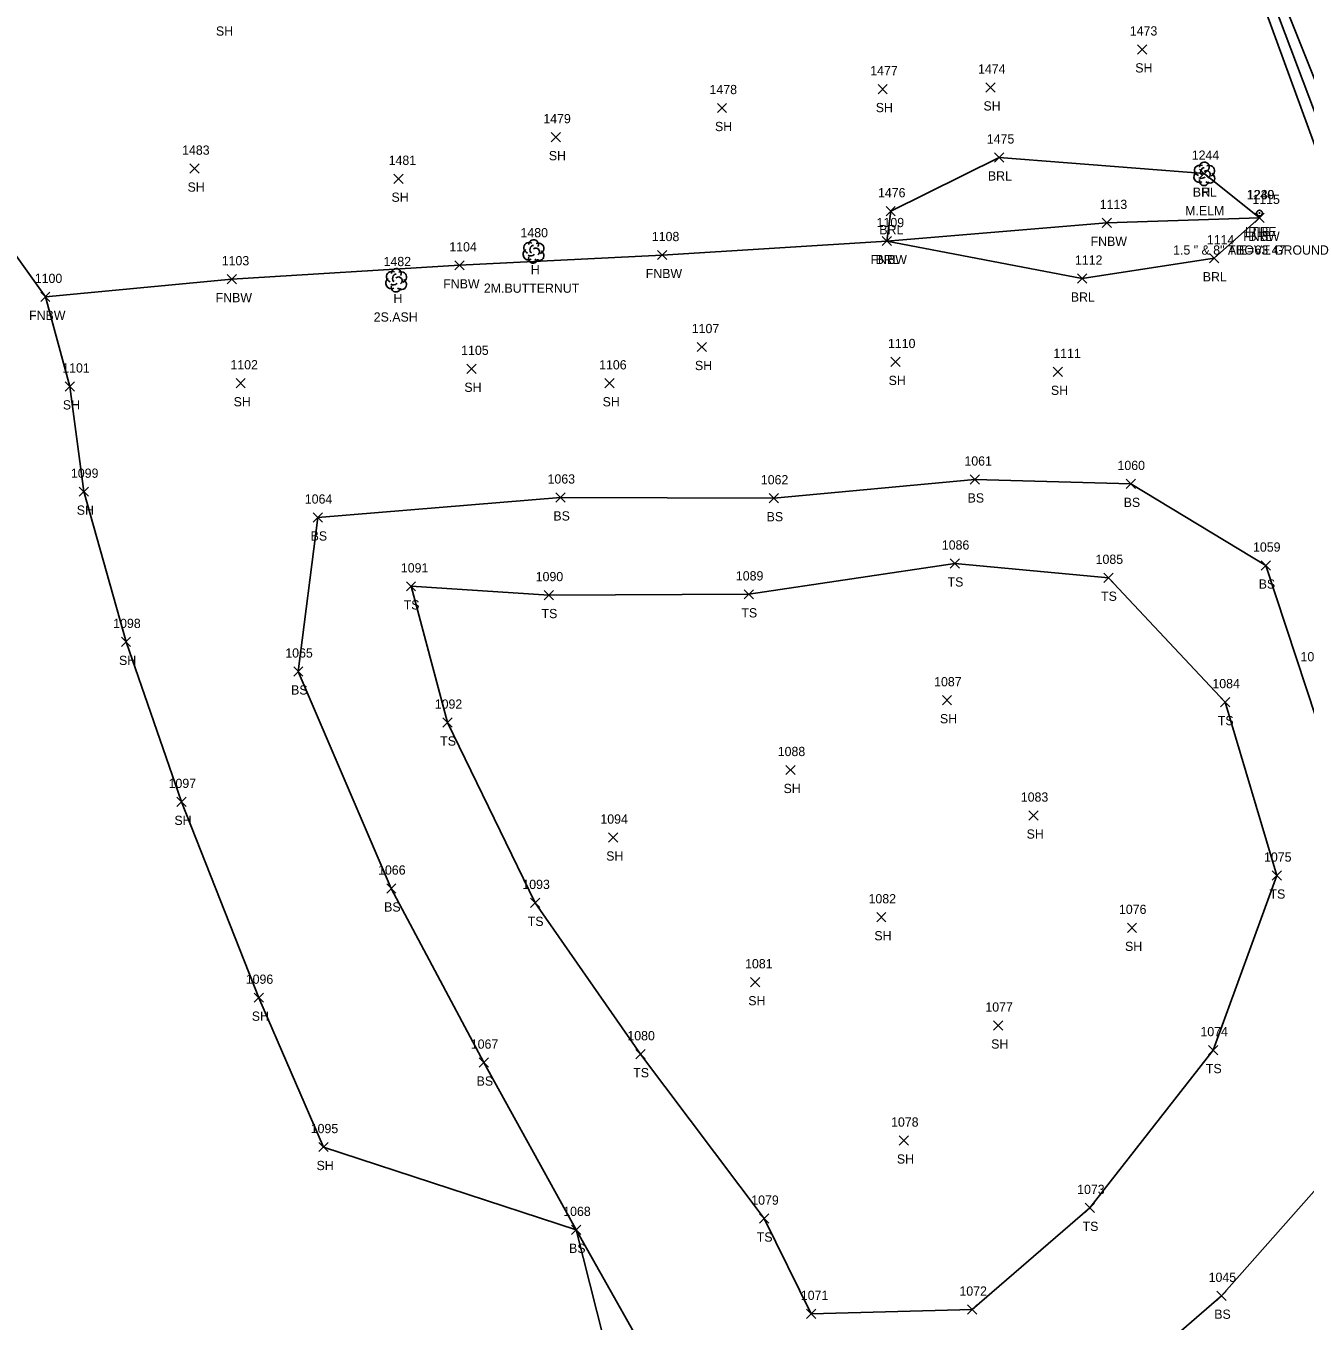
# Model space of a CAD drawing. Extents: x 1472233 to 1475777, y 540726 to 543442.
# Drawn here: x 1475042.8 to 1475319.7, y 542338.7 to 542619 of the extents above; entities that cross this region are included whole.
import ezdxf

# ---------------------------------------------------------------- set-up
doc = ezdxf.new("R2010")
doc.units = 0
for name, color, linetype in [('C_A', 7, 'Continuous'), ('C_C', 7, 'Continuous'), ('C_I', 7, 'Continuous'), ('CBP', 7, 'Continuous'), ('L_A', 7, 'Continuous'), ('L_C', 7, 'Continuous'), ('L_I', 7, 'Continuous'), ('L_TIC', 7, 'Continuous'), ('LABL', 7, 'Continuous'), ('LELB', 7, 'Continuous'), ('LFNC', 7, 'Continuous'), ('LSOGP', 7, 'Continuous'), ('LTD', 7, 'Continuous'), ('M_A', 7, 'Continuous'), ('M_C', 7, 'Continuous'), ('M_I', 7, 'Continuous'), ('MPIP', 7, 'Continuous'), ('PEU', 7, 'Continuous')]:
    doc.layers.add(name, color=color, linetype=linetype)

msp = doc.modelspace()

# ---------------------------------------------------------------- linework, layer by layer
at = {"layer": 'CBP'}
for radius in [0.625, 0.0833]:
    msp.add_circle((1475309.83, 542578.54), radius, dxfattribs=at)
at = {"layer": 'L_TIC'}
for points in [[(1475283.45, 542612.96), (1475285.45, 542614.96)], [(1475285.45, 542612.96), (1475283.45, 542614.96)], [(1475227.27, 542604.37), (1475229.27, 542606.37)], [(1475229.27, 542604.37), (1475227.27, 542606.37)], [(1475250.59, 542604.73), (1475252.59, 542606.73)], [(1475252.59, 542604.73), (1475250.59, 542606.73)], [(1475192.48, 542600.27), (1475194.48, 542602.27)], [(1475194.48, 542600.27), (1475192.48, 542602.27)], [(1475156.51, 542593.97), (1475158.51, 542595.97)], [(1475158.51, 542593.97), (1475156.51, 542595.97)], [(1475252.5, 542589.58), (1475254.5, 542591.58)], [(1475254.5, 542589.58), (1475252.5, 542591.58)], [(1475078.32, 542587.16), (1475080.32, 542589.16)], [(1475080.32, 542587.16), (1475078.32, 542589.16)], [(1475122.46, 542584.97), (1475124.46, 542586.97)], [(1475124.46, 542584.97), (1475122.46, 542586.97)], [(1475296.85, 542586.07), (1475298.85, 542588.07)], [(1475298.85, 542586.07), (1475296.85, 542588.07)], [(1475229, 542577.94), (1475231, 542579.94)], [(1475231, 542577.94), (1475229, 542579.94)], [(1475229, 542577.94), (1475231, 542579.94)], [(1475231, 542577.94), (1475229, 542579.94)], [(1475275.8, 542575.41), (1475277.8, 542577.41)], [(1475277.8, 542575.41), (1475275.8, 542577.41)], [(1475308.85, 542576.51), (1475310.85, 542578.51)], [(1475310.85, 542576.51), (1475308.85, 542578.51)], [(1475308.85, 542576.51), (1475310.85, 542578.51)], [(1475310.85, 542576.51), (1475308.85, 542578.51)], [(1475228.16, 542571.49), (1475230.16, 542573.49)], [(1475230.16, 542571.49), (1475228.16, 542573.49)], [(1475228.16, 542571.49), (1475230.16, 542573.49)], [(1475230.16, 542571.49), (1475228.16, 542573.49)], [(1475228.16, 542571.49), (1475230.16, 542573.49)], [(1475230.16, 542571.49), (1475228.16, 542573.49)], [(1475179.51, 542568.46), (1475181.51, 542570.46)], [(1475181.51, 542568.46), (1475179.51, 542570.46)], [(1475299, 542567.76), (1475301, 542569.76)], [(1475301, 542567.76), (1475299, 542569.76)], [(1475135.67, 542566.23), (1475137.67, 542568.23)], [(1475137.67, 542566.23), (1475135.67, 542568.23)], [(1475086.41, 542563.23), (1475088.41, 542565.23)], [(1475088.41, 542563.23), (1475086.41, 542565.23)], [(1475270.44, 542563.37), (1475272.44, 542565.37)], [(1475272.44, 542563.37), (1475270.44, 542565.37)], [(1475046.02, 542559.41), (1475048.02, 542561.41)], [(1475048.02, 542559.41), (1475046.02, 542561.41)], [(1475188.14, 542548.55), (1475190.14, 542550.55)], [(1475190.14, 542548.55), (1475188.14, 542550.55)], [(1475230.06, 542545.32), (1475232.06, 542547.32)], [(1475232.06, 542545.32), (1475230.06, 542547.32)], [(1475138.24, 542543.84), (1475140.24, 542545.84)], [(1475140.24, 542543.84), (1475138.24, 542545.84)], [(1475265.2, 542543.18), (1475267.2, 542545.18)], [(1475267.2, 542543.18), (1475265.2, 542545.18)], [(1475051.32, 542540.03), (1475053.32, 542542.03)], [(1475053.32, 542540.03), (1475051.32, 542542.03)], [(1475088.29, 542540.71), (1475090.29, 542542.71)], [(1475090.29, 542540.71), (1475088.29, 542542.71)], [(1475168.15, 542540.7), (1475170.15, 542542.7)], [(1475170.15, 542540.7), (1475168.15, 542542.7)], [(1475247.21, 542519.89), (1475249.21, 542521.89)], [(1475249.21, 542519.89), (1475247.21, 542521.89)], [(1475280.99, 542518.93), (1475282.99, 542520.93)], [(1475282.99, 542518.93), (1475280.99, 542520.93)], [(1475054.34, 542517.25), (1475056.34, 542519.25)], [(1475056.34, 542517.25), (1475054.34, 542519.25)], [(1475157.55, 542516), (1475159.55, 542518)], [(1475159.55, 542516), (1475157.55, 542518)], [(1475203.7, 542515.83), (1475205.7, 542517.83)], [(1475205.7, 542515.83), (1475203.7, 542517.83)], [(1475105, 542511.66), (1475107, 542513.66)], [(1475107, 542511.66), (1475105, 542513.66)], [(1475242.9, 542501.71), (1475244.9, 542503.71)], [(1475244.9, 542501.71), (1475242.9, 542503.71)], [(1475310.21, 542501.26), (1475312.21, 542503.26)], [(1475312.21, 542501.26), (1475310.21, 542503.26)], [(1475125.17, 542496.76), (1475127.17, 542498.76)], [(1475127.17, 542496.76), (1475125.17, 542498.76)], [(1475276.13, 542498.62), (1475278.13, 542500.62)], [(1475278.13, 542498.62), (1475276.13, 542500.62)], [(1475155.01, 542494.87), (1475157.01, 542496.87)], [(1475157.01, 542494.87), (1475155.01, 542496.87)], [(1475198.27, 542495.03), (1475200.27, 542497.03)], [(1475200.27, 542495.03), (1475198.27, 542497.03)], [(1475063.48, 542484.74), (1475065.48, 542486.74)], [(1475065.48, 542484.74), (1475063.48, 542486.74)], [(1475100.78, 542478.34), (1475102.78, 542480.34)], [(1475102.78, 542478.34), (1475100.78, 542480.34)], [(1475241.18, 542472.12), (1475243.18, 542474.12)], [(1475243.18, 542472.12), (1475241.18, 542474.12)], [(1475301.4, 542471.71), (1475303.4, 542473.71)], [(1475303.4, 542471.71), (1475301.4, 542473.71)], [(1475133.08, 542467.28), (1475135.08, 542469.28)], [(1475135.08, 542467.28), (1475133.08, 542469.28)], [(1475207.32, 542457.02), (1475209.32, 542459.02)], [(1475209.32, 542457.02), (1475207.32, 542459.02)], [(1475075.47, 542450.12), (1475077.47, 542452.12)], [(1475077.47, 542450.12), (1475075.47, 542452.12)], [(1475259.93, 542447.16), (1475261.93, 542449.16)], [(1475261.93, 542447.16), (1475259.93, 542449.16)], [(1475168.94, 542442.4), (1475170.94, 542444.4)], [(1475170.94, 542442.4), (1475168.94, 542444.4)], [(1475312.59, 542434.17), (1475314.59, 542436.17)], [(1475314.59, 542434.17), (1475312.59, 542436.17)], [(1475120.91, 542431.37), (1475122.91, 542433.37)], [(1475122.91, 542431.37), (1475120.91, 542433.37)], [(1475152.04, 542428.26), (1475154.04, 542430.26)], [(1475154.04, 542428.26), (1475152.04, 542430.26)], [(1475152.04, 542428.26), (1475154.04, 542430.26)], [(1475154.04, 542428.26), (1475152.04, 542430.26)], [(1475226.98, 542425.15), (1475228.98, 542427.15)], [(1475228.98, 542425.15), (1475226.98, 542427.15)], [(1475281.23, 542422.86), (1475283.23, 542424.86)], [(1475283.23, 542422.86), (1475281.23, 542424.86)], [(1475199.68, 542411.09), (1475201.68, 542413.09)], [(1475201.68, 542411.09), (1475199.68, 542413.09)], [(1475092.22, 542407.74), (1475094.22, 542409.74)], [(1475094.22, 542407.74), (1475092.22, 542409.74)], [(1475252.26, 542401.72), (1475254.26, 542403.72)], [(1475254.26, 542401.72), (1475252.26, 542403.72)], [(1475298.81, 542396.4), (1475300.81, 542398.4)], [(1475300.81, 542396.4), (1475298.81, 542398.4)], [(1475140.93, 542393.7), (1475142.93, 542395.7)], [(1475142.93, 542393.7), (1475140.93, 542395.7)], [(1475174.86, 542395.51), (1475176.86, 542397.51)], [(1475176.86, 542395.51), (1475174.86, 542397.51)], [(1475231.86, 542376.83), (1475233.86, 542378.83)], [(1475233.86, 542376.83), (1475231.86, 542378.83)], [(1475106.23, 542375.42), (1475108.23, 542377.42)], [(1475108.23, 542375.42), (1475106.23, 542377.42)], [(1475272.13, 542362.25), (1475274.13, 542364.25)], [(1475274.13, 542362.25), (1475272.13, 542364.25)], [(1475201.6, 542359.93), (1475203.6, 542361.93)], [(1475203.6, 542359.93), (1475201.6, 542361.93)], [(1475160.94, 542357.5), (1475162.94, 542359.5)], [(1475162.94, 542357.5), (1475160.94, 542359.5)], [(1475300.6, 542343.24), (1475302.6, 542345.24)], [(1475302.6, 542343.24), (1475300.6, 542345.24)], [(1475246.65, 542340.25), (1475248.65, 542342.25)], [(1475248.65, 542340.25), (1475246.65, 542342.25)], [(1475211.76, 542339.33), (1475213.76, 542341.33)], [(1475213.76, 542339.33), (1475211.76, 542341.33)], [(1475211.76, 542339.33), (1475213.76, 542341.33)], [(1475213.76, 542339.33), (1475211.76, 542341.33)]]:
    msp.add_lwpolyline(points, dxfattribs=at)
at = {"layer": 'LABL'}
for points in [[(1475229.16, 542572.49), (1475271.44, 542564.37), (1475300, 542568.76), (1475309.85, 542577.51), (1475297.85, 542587.07), (1475253.5, 542590.58), (1475230, 542578.94)], [(1475229.16, 542572.49), (1475230, 542578.94)]]:
    msp.add_lwpolyline(points, dxfattribs=at)
at = {"layer": 'LELB'}
for points in [[(1475471.07, 542235.32), (1475455.73, 542277.51), (1475442.16, 542311.63), (1475427.2, 542345.14), (1475407.3, 542390.99), (1475390.5, 542430.83), (1475365.35, 542490.83), (1475345.68, 542538.17), (1475324.25, 542586.46), (1475305.93, 542636.69)], [(1475477.4, 542237.46), (1475459.38, 542278.29), (1475445.09, 542313.25), (1475430.15, 542346.36), (1475410.48, 542391.41), (1475393.47, 542431.66), (1475368.2, 542491.05), (1475347.92, 542539.36), (1475326.62, 542587.53), (1475308.04, 542636.9)], [(1475200.77, 542308.82), (1475241.78, 542316.68), (1475274.04, 542320.33), (1475301.6, 542344.24), (1475328.33, 542374.36), (1475336.87, 542408.47), (1475330.86, 542442.76), (1475311.21, 542502.26), (1475281.99, 542519.93), (1475248.21, 542520.89), (1475204.7, 542516.83), (1475158.55, 542517), (1475106, 542512.66), (1475101.78, 542479.34), (1475121.91, 542432.37), (1475141.93, 542394.7), (1475161.94, 542358.5), (1475181.79, 542323.33), (1475176.76, 542299.8)], [(1475212.76, 542340.33), (1475247.65, 542341.25), (1475273.13, 542363.25), (1475299.81, 542397.4), (1475313.59, 542435.17), (1475302.4, 542472.71), (1475277.13, 542499.62), (1475243.9, 542502.71), (1475199.27, 542496.03), (1475156.01, 542495.87), (1475126.17, 542497.76), (1475134.08, 542468.28), (1475153.04, 542429.26)], [(1475212.76, 542340.33), (1475202.6, 542360.93), (1475175.86, 542396.51), (1475153.04, 542429.26)]]:
    msp.add_lwpolyline(points, dxfattribs=at)
at = {"layer": 'LFNC'}
msp.add_lwpolyline([(1475047.02, 542560.41), (1475087.41, 542564.23), (1475136.67, 542567.23), (1475180.51, 542569.46), (1475229.16, 542572.49), (1475276.8, 542576.41), (1475309.85, 542577.51)], dxfattribs=at)
at = {"layer": 'LSOGP'}
msp.add_lwpolyline([(1475330.12, 542185), (1475316.58, 542176.31), (1475298.4, 542207.53), (1475277.61, 542235.83), (1475254.76, 542251.05), (1475228.37, 542269.02), (1475176.76, 542299.8), (1475161.94, 542358.5), (1475107.23, 542376.42), (1475093.22, 542408.74), (1475076.47, 542451.12), (1475064.48, 542485.74), (1475055.34, 542518.25), (1475052.32, 542541.03), (1475047.02, 542560.41), (1475029.67, 542584.63)], dxfattribs=at)
at = {"layer": 'LTD'}
for p, q in [((1475297.85, 542587.07), (1475297.85, 542587.07)), ((1475297.85, 542587.07), (1475297.85, 542587.07)), ((1475152.65, 542570.29), (1475152.65, 542570.29)), ((1475152.65, 542570.29), (1475152.65, 542570.29)), ((1475122.92, 542564.05), (1475122.92, 542564.05)), ((1475122.92, 542564.05), (1475122.92, 542564.05))]:
    msp.add_line(p, q, dxfattribs=at)
for centre in [(1475297.9, 542588.5), (1475152.7, 542571.73), (1475122.97, 542565.48)]:
    msp.add_arc(centre, 1.05, 335.5272, 180.9563, dxfattribs=at)
for centre, major_axis, ratio, start_param, end_param in [((1475297.06, 542587.73), (1.21, -0.51), 0.895232, 1.570796, 4.712389), ((1475297.64, 542587.53), (-0.208, -0.792), 0.645439, 3.141593, 6.283185), ((1475298.89, 542587.65), (-1.14, -0.48), 0.949671, 1.570796, 4.712389), ((1475296.77, 542586.36), (0.58, -1.04), 0.959034, 3.141593, 6.283185), ((1475297.85, 542585.57), (0.26, 1.06), 0.942809, 1.570796, 4.712389), ((1475297.39, 542586.32), (-0.625, -0.083), 0.423636, 0, 3.141593), ((1475298.35, 542586.9), (-0.5, 0.667), 0.989748, 3.141593, 6.283185), ((1475298.85, 542586.24), (-1.09, 0.79), 0.841452, 1.570796, 4.712389), ((1475151.86, 542570.96), (1.21, -0.51), 0.895232, 1.570796, 4.712389), ((1475152.44, 542570.75), (-0.208, -0.792), 0.645439, 3.141593, 6.283185), ((1475153.69, 542570.88), (-1.14, -0.48), 0.949671, 1.570796, 4.712389), ((1475151.57, 542569.58), (0.58, -1.04), 0.959034, 3.141593, 6.283185), ((1475152.65, 542568.79), (0.26, 1.06), 0.942809, 1.570796, 4.712389), ((1475152.19, 542569.54), (-0.625, -0.083), 0.423636, 0, 3.141593), ((1475153.15, 542570.13), (-0.5, 0.667), 0.989748, 3.141593, 6.283185), ((1475153.65, 542569.46), (-1.09, 0.79), 0.841452, 1.570796, 4.712389), ((1475122.13, 542564.71), (1.21, -0.51), 0.895232, 1.570796, 4.712389), ((1475123.97, 542564.63), (-1.14, -0.48), 0.949671, 1.570796, 4.712389), ((1475121.84, 542563.34), (0.58, -1.04), 0.959034, 3.141593, 6.283185), ((1475122.47, 542563.3), (-0.625, -0.083), 0.423636, 0, 3.141593), ((1475122.72, 542564.5), (-0.208, -0.792), 0.645439, 3.141593, 6.283185), ((1475123.42, 542563.88), (-0.5, 0.667), 0.989748, 3.141593, 6.283185), ((1475123.92, 542563.21), (-1.09, 0.79), 0.841452, 1.570796, 4.712389), ((1475122.92, 542562.55), (0.26, 1.06), 0.942809, 1.570796, 4.712389)]:
    msp.add_ellipse(centre, major_axis=major_axis, ratio=ratio, start_param=start_param, end_param=end_param, dxfattribs=at)
at = {"layer": 'MPIP'}
for radius in [0.625, 0.0833]:
    msp.add_circle((1475309.83, 542578.54), radius, dxfattribs=at)
at = {"layer": 'PEU'}
msp.add_lwpolyline([(1475479.12, 542237.85), (1475461.93, 542278.83), (1475446.81, 542314.13), (1475433.04, 542347.65), (1475413.19, 542392.06), (1475396.09, 542432.46), (1475370.67, 542491.66), (1475350.46, 542540.4), (1475329.23, 542588.78), (1475309.74, 542637.56), (1475293.45, 542677.97), (1475275.03, 542722.66), (1475253.25, 542774.01), (1475237.56, 542813.36), (1475220.2, 542854.42), (1475196.99, 542908.72), (1475177.68, 542952.09), (1475158.12, 543000.84), (1475137.1, 543050.15), (1475113.34, 543107.63), (1475097.32, 543147.51)], dxfattribs=at)

# ---------------------------------------------------------------- texts
at = {"layer": 'C_A'}
msp.add_text('TIE', height=2, dxfattribs=at).set_placement((1475307.91, 542573.54))
at = {"layer": 'C_C'}
msp.add_text('TIE=63.47', height=2, dxfattribs=at).set_placement((1475303.01, 542569.54))
at = {"layer": 'C_I'}
msp.add_text('1240', height=2, dxfattribs=at).set_placement((1475307.05, 542581.54))
at = {"layer": 'L_A'}
for s, p in [('SH', (1475083.95, 542616.93)), ('SH', (1475282.94, 542608.96)), ('SH', (1475226.76, 542600.37)), ('SH', (1475250.08, 542600.73)), ('SH', (1475191.97, 542596.27)), ('SH', (1475156, 542589.97)), ('BRL', (1475251.04, 542585.58)), ('SH', (1475077.8, 542583.16)), ('SH', (1475121.95, 542580.97)), ('BRL', (1475295.39, 542582.07)), ('H', (1475297.28, 542582.07)), ('BRL', (1475227.54, 542573.94)), ('BRL', (1475227.54, 542573.94)), ('FNBW', (1475306.32, 542572.51)), ('BRL', (1475307.4, 542572.51)), ('FNBW', (1475273.27, 542571.41)), ('FNBW', (1475225.64, 542567.49)), ('BRL', (1475226.71, 542567.49)), ('BRL', (1475226.71, 542567.49)), ('H', (1475152.09, 542565.29)), ('FNBW', (1475176.98, 542564.46)), ('BRL', (1475297.55, 542563.76)), ('FNBW', (1475133.14, 542562.23)), ('FNBW', (1475083.88, 542559.23)), ('H', (1475122.36, 542559.05)), ('BRL', (1475268.99, 542559.37)), ('FNBW', (1475043.5, 542555.41)), ('SH', (1475187.63, 542544.55)), ('SH', (1475229.55, 542541.32)), ('SH', (1475137.72, 542539.84)), ('SH', (1475264.68, 542539.18)), ('SH', (1475050.81, 542536.03)), ('SH', (1475087.78, 542536.71)), ('SH', (1475167.64, 542536.7)), ('SH', (1475053.82, 542513.25)), ('BS', (1475246.65, 542515.89)), ('BS', (1475280.43, 542514.93)), ('BS', (1475156.99, 542512)), ('BS', (1475203.15, 542511.83)), ('BS', (1475104.44, 542507.66)), ('TS', (1475242.31, 542497.71)), ('BS', (1475309.65, 542497.26)), ('TS', (1475275.54, 542494.62)), ('TS', (1475124.58, 542492.76)), ('TS', (1475154.42, 542490.87)), ('TS', (1475197.68, 542491.03)), ('SH', (1475062.97, 542480.74)), ('BS', (1475100.22, 542474.34)), ('SH', (1475240.66, 542468.12)), ('TS', (1475300.81, 542467.71)), ('TS', (1475132.49, 542463.28)), ('SH', (1475206.81, 542453.02)), ('SH', (1475074.96, 542446.12)), ('SH', (1475259.42, 542443.16)), ('SH', (1475168.42, 542438.4)), ('TS', (1475312, 542430.17)), ('BS', (1475120.35, 542427.37)), ('TS', (1475151.45, 542424.26)), ('TS', (1475151.45, 542424.26)), ('SH', (1475226.47, 542421.15)), ('SH', (1475280.72, 542418.86)), ('SH', (1475199.17, 542407.09)), ('SH', (1475091.71, 542403.74)), ('SH', (1475251.75, 542397.72)), ('TS', (1475174.27, 542391.51)), ('TS', (1475298.22, 542392.4)), ('BS', (1475140.37, 542389.7)), ('SH', (1475105.72, 542371.42)), ('SH', (1475231.34, 542372.83)), ('TS', (1475271.54, 542358.25)), ('BS', (1475160.38, 542353.5)), ('TS', (1475201.01, 542355.93)), ('BS', (1475300.04, 542339.24))]:
    msp.add_text(s, height=2, dxfattribs=at).set_placement(p)
at = {"layer": 'L_C'}
for s, p in [('M.ELM', (1475293.75, 542578.07)), ('2M.BUTTERNUT', (1475141.94, 542561.29)), ('2S.ASH', (1475118.1, 542555.05))]:
    msp.add_text(s, height=2, dxfattribs=at).set_placement(p)
at = {"layer": 'L_I'}
for s, p in [('1473', (1475281.76, 542616.96)), ('1474', (1475248.9, 542608.73)), ('1477', (1475225.58, 542608.37)), ('1478', (1475190.79, 542604.27)), ('1479', (1475154.81, 542597.97)), ('1475', (1475250.81, 542593.58)), ('1483', (1475076.62, 542591.16)), ('1481', (1475121.33, 542588.97)), ('1244', (1475295.16, 542590.07)), ('1244', (1475295.16, 542590.07)), ('1476', (1475227.25, 542581.94)), ('1476', (1475227.25, 542581.94)), ('1115', (1475308.29, 542580.51)), ('1115', (1475308.29, 542580.51)), ('1113', (1475275.24, 542579.41)), ('1109', (1475226.95, 542575.49)), ('1109', (1475226.95, 542575.49)), ('1109', (1475226.95, 542575.49)), ('1480', (1475149.87, 542573.29)), ('1108', (1475178.3, 542572.46)), ('1104', (1475134.46, 542570.23)), ('1114', (1475298.44, 542571.76)), ('1103', (1475085.2, 542567.23)), ('1482', (1475120.23, 542567.05)), ('1112', (1475269.88, 542567.37)), ('1100', (1475044.73, 542563.41)), ('1107', (1475186.94, 542552.55)), ('1105', (1475137.03, 542547.84)), ('1110', (1475229.41, 542549.32)), ('1111', (1475265.2, 542547.18)), ('1102', (1475087.08, 542544.71)), ('1106', (1475166.89, 542544.7)), ('1101', (1475050.68, 542544.03)), ('1061', (1475245.96, 542523.89)), ('1060', (1475279.09, 542522.93)), ('1099', (1475052.56, 542521.25)), ('1063', (1475155.73, 542520)), ('1062', (1475201.89, 542519.83)), ('1064', (1475103.18, 542515.66)), ('1086', (1475241.07, 542505.71)), ('1059', (1475308.43, 542505.26)), ('1085', (1475274.36, 542502.62)), ('1091', (1475123.97, 542500.76)), ('1090', (1475153.16, 542498.87)), ('1089', (1475196.49, 542499.03)), ('1098', (1475061.71, 542488.74)), ('1065', (1475098.96, 542482.34)), ('1058', (1475318.71, 542481.54)), ('1087', (1475239.4, 542476.12)), ('1084', (1475299.63, 542475.71)), ('1092', (1475131.31, 542471.28)), ('1088', (1475205.55, 542461.02)), ('1097', (1475073.7, 542454.12)), ('1083', (1475258.16, 542451.16)), ('1094', (1475167.16, 542446.4)), ('1075', (1475310.81, 542438.17)), ('1066', (1475119.04, 542435.37)), ('1093', (1475150.27, 542432.26)), ('1093', (1475150.27, 542432.26)), ('1082', (1475225.21, 542429.15)), ('1076', (1475279.41, 542426.86)), ('1081', (1475198.48, 542415.09)), ('1096', (1475090.4, 542411.74)), ('1077', (1475250.49, 542405.72)), ('1080', (1475173, 542399.51)), ('1074', (1475297.04, 542400.4)), ('1067', (1475139.11, 542397.7)), ('1095', (1475104.46, 542379.42)), ('1078', (1475230.08, 542380.83)), ('1073', (1475270.36, 542366.25)), ('1079', (1475199.82, 542363.93)), ('1068', (1475159.12, 542361.5)), ('1045', (1475298.82, 542347.24)), ('1071', (1475210.55, 542343.33)), ('1071', (1475210.55, 542343.33)), ('1072', (1475244.88, 542344.25))]:
    msp.add_text(s, height=2, dxfattribs=at).set_placement(p)
at = {"layer": 'M_A'}
msp.add_text('IPIPE', height=2, dxfattribs=at).set_placement((1475306.66, 542573.54))
at = {"layer": 'M_C'}
msp.add_text('1.5 " & 8" ABOVE GROUND', height=2, dxfattribs=at).set_placement((1475291.13, 542569.54))
at = {"layer": 'M_I'}
msp.add_text('1239', height=2, dxfattribs=at).set_placement((1475307.13, 542581.54))

doc.saveas('drawing.dxf')
